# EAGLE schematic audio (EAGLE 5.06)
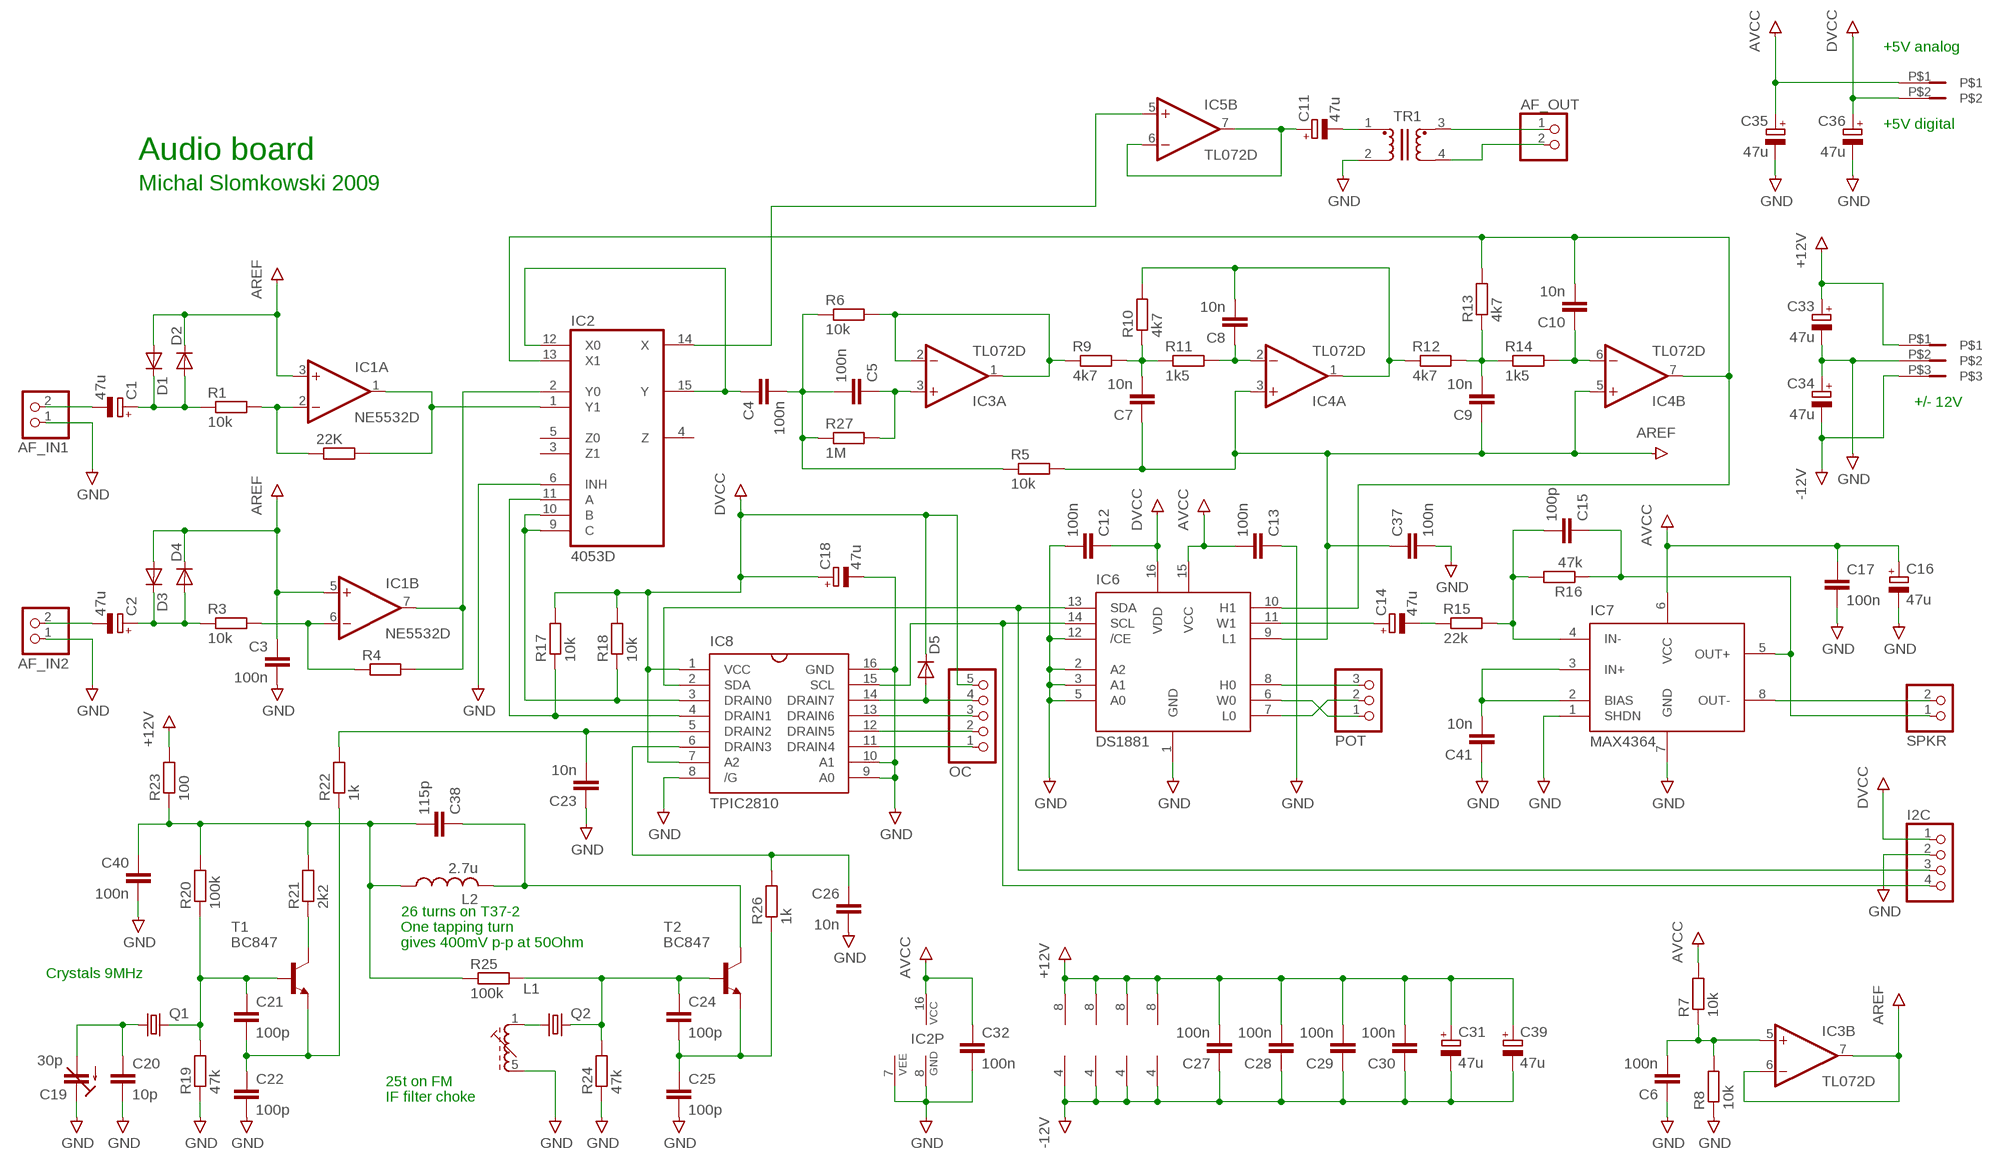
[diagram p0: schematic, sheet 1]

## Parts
22K  R-EU_R1206  [R1206]
AF_IN1  PINHD-1X2  [1X02]
AF_IN2  PINHD-1X2  [1X02]
AF_OUT  PINHD-1X2  [1X02]
C1  47u  CPOL-EUE2.5-6  [E2,5-6]
C2  47u  CPOL-EUE2.5-6  [E2,5-6]
C3  100n  C-EUC1206  [C1206]
C4  100n  C-EUC1206  [C1206]
C5  100n  C-EUC1206  [C1206]
C6  100n  C-EUC1206  [C1206]
C7  10n  C-EUC1206  [C1206]
C8  10n  C-EUC1206  [C1206]
C9  10n  C-EUC1206  [C1206]
C10  10n  C-EUC1206  [C1206]
C11  47u  CPOL-EUE2.5-6  [E2,5-6]
C12  100n  C-EUC1206  [C1206]
C13  100n  C-EUC1206  [C1206]
C14  47u  CPOL-EUE2.5-6  [E2,5-6]
C15  100p  C-EUC1206  [C1206]
C16  47u  CPOL-EUE2.5-6  [E2,5-6]
C17  100n  C-EUC1206  [C1206]
C18  47u  CPOL-EUE2.5-6  [E2,5-6]
C19  30p  C-TRIMM808-1  [CTRIM808-1]
C20  10p  C-EUC1206  [C1206]
C21  100p  C-EUC1206  [C1206]
C22  100p  C-EUC1206  [C1206]
C23  10n  C-EUC1206  [C1206]
C24  100p  C-EUC1206  [C1206]
C25  100p  C-EUC1206  [C1206]
C26  10n  C-EUC1206  [C1206]
C27  100n  C-EUC1206  [C1206]
C28  100n  C-EUC1206  [C1206]
C29  100n  C-EUC1206  [C1206]
C30  100n  C-EUC1206  [C1206]
C31  47u  CPOL-EUE2.5-6  [E2,5-6]
C32  100n  C-EUC1206  [C1206]
C33  47u  CPOL-EUE2.5-6  [E2,5-6]
C34  47u  CPOL-EUE2.5-6  [E2,5-6]
C35  47u  CPOL-EUE2.5-6  [E2,5-6]
C36  47u  CPOL-EUE2.5-6  [E2,5-6]
C37  100n  C-EUC1206  [C1206]
C38  115p  C-EUC1206  [C1206]
C39  47u  CPOL-EUE2.5-6  [E2,5-6]
C40  100n  C-EUC1206  [C1206]
C41  10n  C-EUC0805  [C0805]
D1  PMLL4150  [SOD80C]
D2  PMLL4150  [SOD80C]
D3  PMLL4150  [SOD80C]
D4  PMLL4150  [SOD80C]
D5  PMLL4150  [SOD80C]
I2C  PINHD-1X4  [1X04]
IC1  NE5532D  [SO08]
IC2  4053D  [SO16]
IC3  TL072D  [SO08]
IC4  TL072D  [SO08]
IC5  TL072D  [SO08]
IC6  DS1881  [SO16]
IC7  MAX4364  [SO08]
IC8  TPIC2810  [SO16]
L1  51K  [71K]
L2  2.7u  L-US0204/5  [0204/5]
OC  PINHD-1X5  [1X05]
POT  PINHD-1X3  [1X03]
Q1  CRYTALHC49U-V  [HC49U-V]
Q2  CRYTALHC49U-V  [HC49U-V]
R1  10k  R-EU_R1206  [R1206]
R3  10k  R-EU_R1206  [R1206]
R4  R-EU_R1206  [R1206]
R5  10k  R-EU_R1206  [R1206]
R6  10k  R-EU_R1206  [R1206]
R7  10k  R-EU_R1206  [R1206]
R8  10k  R-EU_R1206  [R1206]
R9  4k7  R-EU_R1206  [R1206]
R10  4k7  R-EU_R1206  [R1206]
R11  1k5  R-EU_R1206  [R1206]
R12  4k7  R-EU_R1206  [R1206]
R13  4k7  R-EU_R1206  [R1206]
R14  1k5  R-EU_R1206  [R1206]
R15  22k  R-EU_R1206  [R1206]
R16  47k  R-EU_R1206  [R1206]
R17  10k  R-EU_R1206  [R1206]
R18  10k  R-EU_R1206  [R1206]
R19  47k  R-EU_R1206  [R1206]
R20  100k  R-EU_R1206  [R1206]
R21  2k2  R-EU_R1206  [R1206]
R22  1k  R-EU_R1206  [R1206]
R23  100  R-EU_R1206  [R1206]
R24  47k  R-EU_R1206  [R1206]
R25  100k  R-EU_R1206  [R1206]
R26  1k  R-EU_R1206  [R1206]
R27  1M  R-EU_R1206  [R1206]
SPKR  PINHD-1X2  [1X02]
T1  BC847  [SOT23]
T2  BC847  [SOT23]
TR1  TRANSFORMER  [TRANSFORMER]
U$1  RIACON-3  [RIACON-3]
U$2  RIACON-2  [RIACON-2]

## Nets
GND: AF_IN1.1 AF_IN2.1 C3.2 C6.1 C12.2 C13.1 C16.- C17.2 C18.- C19.1(E) C20.2 C22.2 C23.1 C25.2 C26.2 C32.2 C33.- C34.+ C35.- C36.- C37.2 C40.2 C41.1 I2C.2 IC2.6(INH) IC2.7(VEE) IC2.8(GND) IC6.1(GND) IC6.2(A2) IC6.3(A1) IC6.5(A0) IC6.12(/CE) IC7.1(SHDN) IC7.7(GND) IC8.8(/G) IC8.9(A0) IC8.10(A1) IC8.16(GND) L1.5(E) R8.1 R19.1 R24.1 TR1.2 U$1.P$2
N$1: AF_IN1.2 C1.-
N$2: AF_IN2.2 C2.-
N$3: C1.+ D1.C D2.A R1.1
N$4: 22K.1 IC1.2(A:-IN) R1.2
N$6: IC1.6(B:-IN) R3.2 R4.1
N$7: IC1.7(B:OUT) IC2.2(Y0) R4.2
N$8: C2.+ D3.C D4.A R3.1
N$9: IC6.6(W0) POT.1
N$11: C5.1 IC3.3(A:+IN) R27.2
N$12: C4.1 IC2.12(X0) IC2.15(Y)
N$14: C7.2 R9.2 R10.1 R11.1
N$15: C8.1 IC4.2(A:-IN) R11.2
N$16: C8.2 IC4.1(A:OUT) R10.2 R12.1
N$17: C11.+ IC5.6(B:-IN) IC5.7(B:OUT)
N$19: C10.1 IC4.6(B:-IN) R14.2
N$20: C11.- TR1.1
N$22: IC2.14(X) IC5.5(B:+IN)
N$23: AF_OUT.1 TR1.3
N$24: AF_OUT.2 TR1.4
N$25: IC7.8(OUT-) SPKR.2
N$26: I2C.4 IC6.14(SCL) IC8.15(SCL)
N$27: C14.+ IC6.11(W1)
N$28: C14.- R15.1
N$29: C15.2 IC7.4(IN-) R15.2 R16.2
N$30: I2C.3 IC6.13(SDA) IC8.2(SDA)
N$31: C15.1 IC7.5(OUT+) R16.1 SPKR.1
N$32: C41.2 IC7.2(BIAS) IC7.3(IN+)
N$33: IC6.8(H0) POT.3
N$34: IC6.7(L0) POT.2
N$38: L1.1(A) Q2.1
N$39: C19.2(A) C20.1 Q1.1
N$40: C24.1 Q2.2 R24.2 R25.2 T2.1(B)
N$41: C21.2 C22.1 R22.1 T1.2(E)
N$44: C24.2 C25.1 R26.1 T2.2(E)
N$45: C27.1 C28.1 C29.1 C30.1 C31.- C34.- C39.- IC1.4(P:V-) IC3.4(P:V-) IC4.4(P:V-) IC5.4(P:V-) U$1.P$3 ; supply symbol labelled -12V
N$46: C21.1 Q1.2 R19.2 R20.1 T1.1(B)
N$47: IC8.13(DRAIN6) OC.3
N$48: C23.2 IC8.5(DRAIN2) R22.2
N$49: C26.1 IC8.6(DRAIN3) R26.2
N$52: IC8.11(DRAIN4) OC.1
N$53: D5.A IC8.14(DRAIN7) OC.4
N$59: IC2.9(C) IC2.10(B) IC8.3(DRAIN0) R18.1
N$61: IC8.12(DRAIN5) OC.2
N$80: C9.2 R12.2 R13.1 R14.1
N$83: C10.2 IC2.13(X1) IC4.7(B:OUT) IC6.10(H1) R13.2
N$88: 22K.2 IC1.1(A:OUT) IC2.1(Y1)
N$96: IC3.1(A:OUT) IC3.2(A:-IN) R6.2 R9.1
N$117: C4.2 C5.2 R5.1 R6.1 R27.1
N$126: C13.2 C16.+ C17.1 C32.1 C35.+ IC2.16(VCC) IC6.15(VCC) IC7.6(VCC) R7.2 U$2.P$1 ; supply symbol labelled AVCC
N$138: C6.2 IC3.5(B:+IN) R7.1 R8.2
N$143: C3.1 C7.1 C9.1 C37.1 D1.A D2.C D3.A D4.C IC1.3(A:+IN) IC1.5(B:+IN) IC3.6(B:-IN) IC3.7(B:OUT) IC4.3(A:+IN) IC4.5(B:+IN) IC6.9(L1) R5.2 ; supply symbol labelled AREF
N$172: R21.1 T1.3(C)
N$223: C12.1 C18.+ C36.+ D5.C I2C.1 IC6.16(VDD) IC8.1(VCC) IC8.7(A2) OC.5 R17.2 R18.2 U$2.P$2 ; supply symbol labelled DVCC
N$228: IC2.11(A) IC8.4(DRAIN1) R17.1
N$235: C38.2 C40.1 L2.1 R20.2 R21.2 R23.1 R25.1
N$252: C27.2 C28.2 C29.2 C30.2 C31.+ C33.+ C39.+ IC1.8(P:V+) IC3.8(P:V+) IC4.8(P:V+) IC5.8(P:V+) R23.2 U$1.P$1 ; supply symbol labelled +12V
N$264: C38.1 L2.2 T2.3(C)
Unconnected: IC2.3(Z1) IC2.4(Z) IC2.5(Z0) IC5.1(A:OUT) IC5.2(A:-IN) IC5.3(A:+IN) L1.S1(S2) L1.S2(S1)

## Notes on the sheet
- +5V analog
- +5V digital
- Audio board
- Michal Slomkowski 2009
- +/- 12V
- 26 turns on T37-2
- One tapping turn
- gives 400mV p-p at 50Ohm
- Crystals 9MHz
- 25t on FM
- IF filter choke

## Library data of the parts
22K R1 R3-R27 = rcl:R-EU_: RESISTOR, European symbol
AF_IN1 AF_IN2 AF_OUT SPKR = pinhead:PINHD-1X2: PIN HEADER
C1 C2 C11 C14 C16 C18 C31 C33-C36 C39 = rcl:CPOL-EU: POLARIZED CAPACITOR, European symbol
C3-C10 C12 C13 C15 C17 C20-C30 C32 C37 C38 C40 C41 = rcl:C-EU: CAPACITOR, European symbol
C19 = rcl:C-TRIMM: Trimm capacitor
D1-D5 = diode:PMLL4150: DIODE
I2C = pinhead:PINHD-1X4: PIN HEADER
IC1 = linear:NE5532: AUDIO AMPLIFIER
IC2 = 40xx:4053: Triple 2-channel ANALOG MULTIPLEXER
IC3-IC5 = linear:TL072: OP AMP
IC6 = receiver:DS1881
IC7 = receiver:MAX4364
IC8 = receiver:TPIC2810: 8-Bit LED Driver with I2C Interface
L1 = inductor-neosid:51K: FILTER pre-adjusted RF filter, type K, standard value E-12
L2 = rcl:L-US: INDUCTOR, American symbol
OC = pinhead:PINHD-1X5: PIN HEADER
POT = pinhead:PINHD-1X3: PIN HEADER
Q1 Q2 = crystal:CRYTAL: CRYSTAL
T1 T2 = transistor:BC847: NPN TRANSISTOR
TR1 = receiver:TRANSFORMER: DIGITAL AUDIO DATA TX TRANSFORMER AES 3-199X or IEC 958
U$1 = con-riacon:RIACON-3
U$2 = con-riacon:RIACON-2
